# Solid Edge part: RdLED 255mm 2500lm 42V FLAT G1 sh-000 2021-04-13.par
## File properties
Author: radoslaw.kuczynski
Template: iso metric part.par
Last saved by: radoslaw.kuczynski
Revision: 1
Application: Solid Edge
Gęstość: 0.000 kg/m^3
Dokładność: 0.990
Username: radoslaw.kuczynski
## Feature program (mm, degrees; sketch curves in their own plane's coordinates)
body "unnamed Body 1"
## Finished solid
Body 1: solid body, 2676 faces, 6917 edges, 4516 vertices.
  Faces by surface: plane 2330, cylinder 136, spline 81, swept 75, cone 26, torus 11, sphere 10, spun 7
  Edges by curve: line 6173, curve on surface 423, circle 191, ellipse 66, spline 58, intersection 6
Bounding box of the edges (mm; curved faces can reach further): 247.000 x 4.450 x 247.000, from (-123.5, -3.45, -123.5) to (123.5, 1, 123.5).
Cylindrical faces by radius (mm): R0.2 x39, R0.2002 x2, R0.2169 x3, R0.25 x12, R0.3 x2, R0.3373 x3, R0.4 x8, R0.4006 x2, R0.4008 x2, R0.525 x2, R0.6 x12, R0.75 x1, R1 x7, R1.0894 x2, R1.1 x14, R1.15 x2, R1.25 x2, R1.7689 x1, R2 x2, R2.15 x12, R3 x1, R3.05 x1, R127.5 x4
Conical faces (half-angle, radius in mm at the cone's reference point): 0.5 deg R0.5056 x4, 0.5 deg R1.0082 x4, 1 deg R0.5511 x2, 10 deg R0.2132 x2, 10 deg R0.4132 x2, 18.4844 deg R1.0657 x4, 27.363 deg R0.6214 x2, 45 deg R0.575 x2, 45 deg R0.625 x4
Toroidal faces (ring radius, tube radius in mm): R0.1 r0.2 x1, R0.8 r0.2 x4, R0.8522 r0.3 x2, R0.9002 r0.2 x1, R0.9018 r0.2 x1, R1.3 r0.2 x2
Spherical faces by radius (mm): R0.2 x8, R0.6 x2
Planar faces by outward normal: +x 107, +y 8, +z 104, -x 96, -y 427, -z 95, oblique 1493
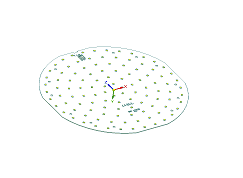
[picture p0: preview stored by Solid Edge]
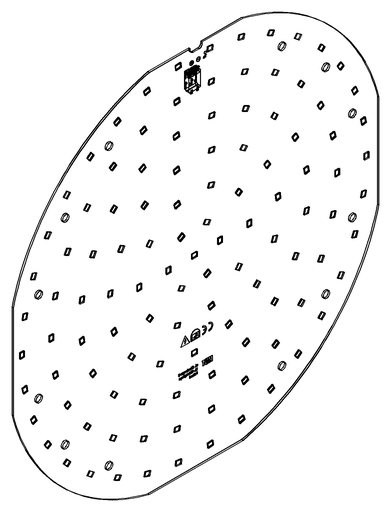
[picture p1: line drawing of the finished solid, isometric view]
